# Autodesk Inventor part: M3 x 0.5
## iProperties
IsCustomPart: 0
Created: 2009-02
Part Number: M3 x 0.5
Material: 강, 연강
Description: 6각머리 태핑 나사
Document SubType Name: Modeling
Standard: KS B 1003
Designer: SeoGD™
Standards Organization: KS
Language: ko-KR
Size Designation: M 3 x 12
Categories: <MemberInstance><Categories><Category DisplayName="조임쇠" InternalName="e4da775c-781d-43d5-af7c-5136215cf5a6" Mnemonic="FSTN"><Category DisplayName="볼트" InternalN
Density: 1 g/cm^3
Author: SeoGD™
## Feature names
1. Fillet2
